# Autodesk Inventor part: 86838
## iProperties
Created: 2005-11
Part Number: 86838
Material: 1.4301 X5CrNi10-10 A2
Description: Flexible Vakuumschläuch  DN 100 ISO-K, 250lg.
Document SubType Name: Modellieren
Designer: Mittelmeyer
Manufacturer: Standard
Standards Organization: Custom
Vendor: LEYBOLD
Author: Mittelmeyer
Comments: LEYBOLD
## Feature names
1. Extrusion2
2. Extrusion3
3. Extrusion4
4. Drehung1 [Revolution]
5. Bohrung1 [Hole]
6. Drehung2 [Revolution]
7. Rundung3 [Fillet]
8. Rechteckige Anordnung1 [Rectangular Pattern]
9. Spiegeln1 [Mirror]
